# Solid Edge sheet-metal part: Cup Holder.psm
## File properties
Author: m_hel
Template: Iso Metric Sheet Metal.psm
Last saved by: m_hel
Revision: 2
Application: Solid Edge
Username: m_hel
Accuracy: 0,990
Material Thickness: 2,00 mm
Bend Radius: 1,00 mm
Relief Width: 1,00 mm
Relief Length: 0,00 mm
Neutral Factor: 0,330
Minimum Arc Length: 0,10 mm
Deviational Tolerance: 0,10 mm
Material: Chrome
Face Style: Chrome
Fill Style: Normal
Virtual Style: Normal
Grouping: Uncategorized
LibraryName: Custom Materials
Coef. of Thermal Exp: 0.0
Thermal Conductivity: 0.0
Specific Heat: 0.0
Modulus of Elasticity: 0.0
Poisson's Ratio: 0.0
Yield Stress: 0.0
Ultimate Stress: 0.0
Elongation: 0.0
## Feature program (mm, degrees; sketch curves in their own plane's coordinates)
base tab "unnamed BaseTab 1"
dimple "Dimple_1"
dimple "Dimple_2"
sketch for "unnamed Cutout 1" plane through (0, 0, -48) normal (0, 0, 1) x-axis (1, 0, 0)
  circle centre (0, 0) radius 20
extrude "unnamed Cutout 1" cut
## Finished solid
Body 1: solid body, 16 faces, 16 edges, 0 vertices.
  Faces by surface: plane 6, cylinder 4, torus 4, cone 2
  Edges by curve: circle 16
Bounding box of the edges (mm; curved faces can reach further): 90.000 x 90.000 x 57.000, from (-45, -45, -55) to (45, 45, 2).
Cylindrical faces by radius (mm): R20 x1, R25.5 x1, R27.5 x1, R45 x1
Conical faces (half-angle, radius in mm at the cone's reference point): 5 deg R30.5076 x1, 5 deg R32.5 x1
Toroidal faces (ring radius, tube radius in mm): R25.5 r2 x1, R27.5 r2 x1, R30.6673 r2 x1, R36.8744 r2 x1
Planar faces by outward normal: +z 3, -z 3
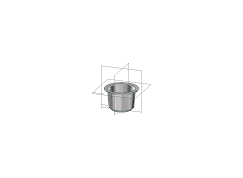
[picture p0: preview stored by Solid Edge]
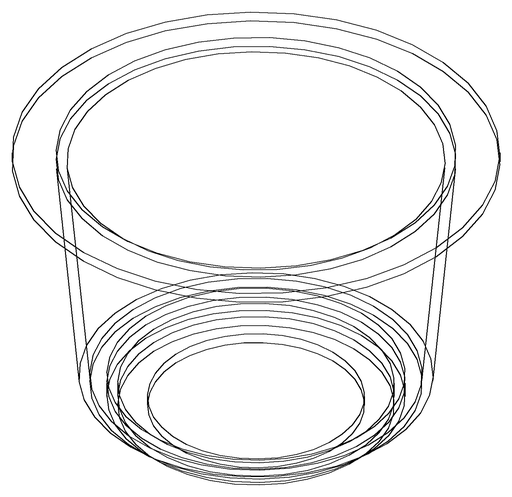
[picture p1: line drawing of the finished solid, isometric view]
